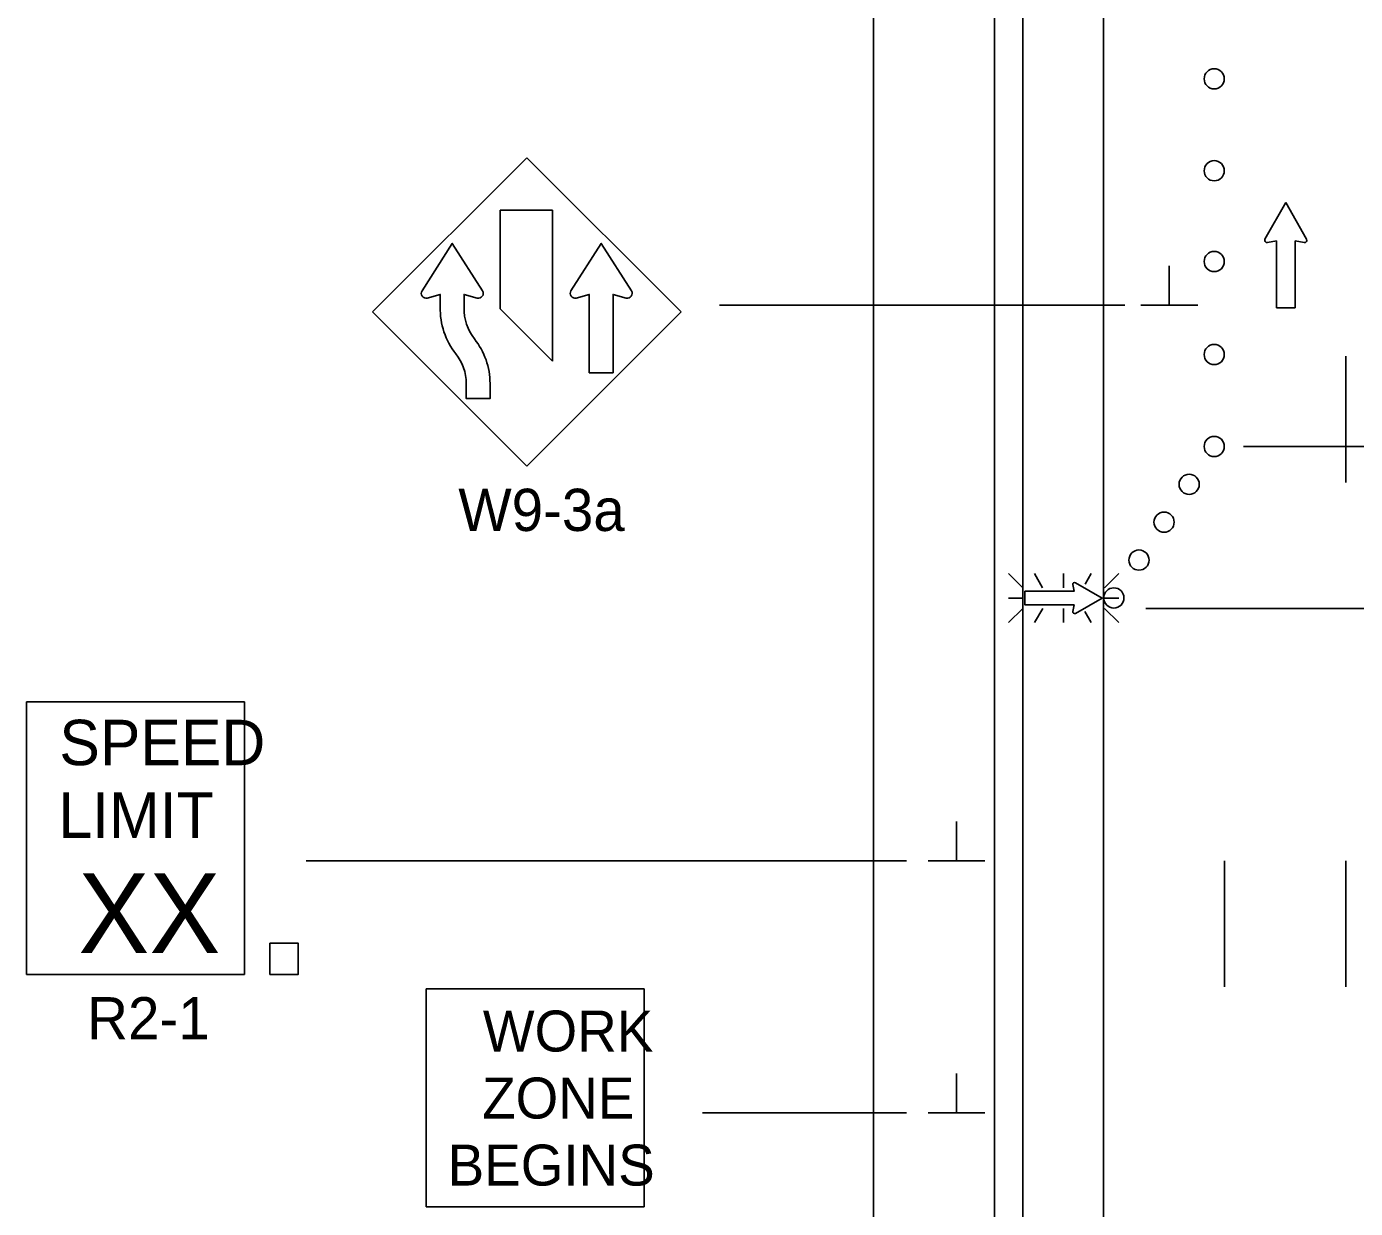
# Model space of a CAD drawing. Extents: x 16737 to 18482, y 6986 to 8195.
# Drawn here: x 16812.9 to 17076.2, y 7597.3 to 7831.6 of the extents above; entities that cross this region are included whole.
import ezdxf

# ---------------------------------------------------------------- set-up
doc = ezdxf.new("R2010")
doc.units = 0
for name, color, linetype in [('ALI_LEGAL_EX', 7, 'Continuous'), ('MT_SCRATCH_LEVEL_E', 7, 'Continuous'), ('PAVT_EDGE_EX', 7, 'Continuous'), ('TRAFFIC_SIGNS_PR', 7, 'Continuous'), ('TYPICAL_TEXT_DIMEN_PR', 7, 'Continuous')]:
    doc.layers.add(name, color=color, linetype=linetype)

msp = doc.modelspace()

# ---------------------------------------------------------------- linework, layer by layer
at = {"layer": 'ALI_LEGAL_EX'}
for p, q in [((16980.68, 8182.43), (16980.68, 7364.3)), ((17004.68, 8182.43), (17004.68, 7364.3))]:
    msp.add_line(p, q, dxfattribs=at)
for points in [[(17074.25, 7766.21), (17074.25, 7741.21)], [(17050.25, 7666.21), (17050.25, 7641.21)], [(17074.25, 7666.21), (17074.25, 7641.21)]]:
    msp.add_lwpolyline(points, dxfattribs=at)
at = {"layer": 'MT_SCRATCH_LEVEL_E'}
for p, q in [((17062.35, 7796.66), (17058.24, 7789.42)), ((17066.5, 7789.42), (17062.35, 7796.66)), ((17058.73, 7788.74), (17060.5, 7789.06)), ((17060.5, 7789.06), (17060.5, 7775.8)), ((17064.24, 7775.8), (17064.24, 7789.06)), ((17064.24, 7789.06), (17066.02, 7788.74)), ((17060.5, 7775.8), (17064.24, 7775.8))]:
    msp.add_line(p, q, dxfattribs=at)
for centre, start, end in [((17058.65, 7789.2), 150.4248, 279.9638), ((17066.09, 7789.2), 260.0362, 29.7731)]:
    msp.add_arc(centre, 0.463, start, end, dxfattribs=at)
at = {"layer": 'PAVT_EDGE_EX'}
for p, q in [((17010.25, 8166.21), (17010.25, 7372.95)), ((17026.25, 8166.21), (17026.25, 7372.95))]:
    msp.add_line(p, q, dxfattribs=at)
at = {"layer": 'TRAFFIC_SIGNS_PR'}
for p, q in [((16912.01, 7805.55), (16881.46, 7775)), ((16942.56, 7775), (16912.01, 7805.55)), ((16906.71, 7795.17), (16906.71, 7775.6)), ((16917.07, 7795.17), (16906.71, 7795.17)), ((16917.07, 7765.24), (16917.07, 7795.17)), ((16881.46, 7775), (16912.01, 7744.45)), ((16906.71, 7775.6), (16917.07, 7765.24)), ((16912.01, 7744.45), (16942.56, 7775)), ((17010.27, 7720.3), (17007.45, 7723.12)), ((17012.56, 7723.12), (17014.19, 7720.3)), ((17018.35, 7720.3), (17018.35, 7723.12)), ((17023.82, 7723.12), (17022.62, 7721.03)), ((17029.26, 7723.12), (17026.44, 7720.3)), ((17010.27, 7718.27), (17007.45, 7718.27)), ((17010.27, 7716.24), (17007.45, 7713.41)), ((17014.22, 7716.24), (17012.59, 7713.42)), ((17018.35, 7716.24), (17018.35, 7713.42)), ((17026.44, 7718.27), (17029.26, 7718.27)), ((17029.26, 7713.42), (17026.44, 7716.24)), ((17022.54, 7715.6), (17023.8, 7713.42)), ((16812.9, 7697.69), (16856.1, 7697.69)), ((16812.9, 7643.69), (16812.9, 7697.69)), ((16856.1, 7643.69), (16856.1, 7697.69)), ((16812.9, 7643.69), (16856.1, 7643.69)), ((16892.04, 7597.63), (16892.04, 7640.83)), ((16892.04, 7640.83), (16935.24, 7640.83)), ((16935.24, 7597.63), (16935.24, 7640.83)), ((16892.04, 7597.63), (16935.24, 7597.63))]:
    msp.add_line(p, q, dxfattribs=at)
for points in [[(16903.23, 7779.17), (16897.23, 7788.58), (16891.24, 7779.17)], [(16932.73, 7779.17), (16926.74, 7788.58), (16920.75, 7779.17)], [(16892.29, 7777.75), (16894.87, 7778.46), (16894.87, 7775.95)], [(16899.59, 7775.83), (16899.59, 7778.46), (16902.18, 7777.75)], [(16921.8, 7777.75), (16924.38, 7778.46), (16924.38, 7762.93), (16929.1, 7762.93), (16929.1, 7778.46), (16931.69, 7777.75)], [(16900.01, 7760.81), (16900, 7757.83), (16904.73, 7757.83), (16904.73, 7760.81)], [(17020.18, 7720.95), (17020.41, 7719.65), (17010.69, 7719.65), (17010.69, 7716.91), (17020.41, 7716.91), (17020.18, 7715.61)], [(17020.68, 7715.25), (17025.99, 7718.27), (17020.68, 7721.31)]]:
    msp.add_lwpolyline(points, dxfattribs=at)
msp.add_lwpolyline([(16861.12, 7643.69), (16866.71, 7643.69), (16866.71, 7649.86), (16861.12, 7649.86)], close=True, dxfattribs=at)
for centre in [(17048.19, 7821.19), (17048.19, 7802.98), (17048.19, 7784.98), (17048.19, 7766.55), (17048.19, 7748.33), (17043.22, 7740.82), (17038.25, 7733.32), (17033.28, 7725.81), (17028.31, 7718.31)]:
    msp.add_circle(centre, 2, dxfattribs=at)
for centre, radius, start, end in [((16892.04, 7778.66), 0.945, 147.5204, 285.3986), ((16902.43, 7778.66), 0.947, 254.6828, 32.2708), ((16899.06, 7766.36), 11.81, 74.68, 74.6808), ((16913.19, 7785.51), 11.81, 212.4569, 212.4665), ((16921.55, 7778.66), 0.946, 147.5497, 285.3316), ((16931.94, 7778.66), 0.943, 254.6778, 32.4665), ((16942.7, 7785.51), 11.81, 212.4569, 212.4665), ((16909.03, 7775.53), 14.17, 178.3293, 218.5427), ((16909.03, 7775.53), 9.45, 178.1936, 218.5465), ((16887.78, 7776.21), 11.81, 358.1894, 0.0048), ((16890.55, 7760.81), 14.17, 0, 38.5422), ((16890.55, 7760.81), 9.45, 0, 38.5457), ((17020.52, 7721.01), 0.341, 61.4833, 189.9593), ((17020.51, 7715.55), 0.341, 170.7308, 298.8916)]:
    msp.add_arc(centre, radius, start, end, dxfattribs=at)
at = {"layer": 'TYPICAL_TEXT_DIMEN_PR'}
for p, q in [((17039.29, 7776.36), (17039.29, 7784.15)), ((17030.46, 7776.36), (16950.18, 7776.36)), ((17044.92, 7776.36), (17033.67, 7776.36)), ((17054, 7748.33), (17198.06, 7748.33)), ((17034.65, 7716.23), (17163.25, 7716.23)), ((16997.12, 7666.23), (16997.12, 7674.02)), ((16868.3, 7666.23), (16987.25, 7666.23)), ((16991.5, 7666.23), (17002.75, 7666.23)), ((16997.12, 7616.23), (16997.12, 7624.02)), ((16987.25, 7616.23), (16946.83, 7616.23)), ((16991.5, 7616.23), (17002.75, 7616.23))]:
    msp.add_line(p, q, dxfattribs=at)

# ---------------------------------------------------------------- texts
at = {"layer": 'TRAFFIC_SIGNS_PR'}
for s, height, p in [('W9-3a', 8.37, (16898.44, 7731.58)), ('SPEED', 9, (16819.39, 7685.16)), ('LIMIT', 9, (16819.21, 7670.76)), ('XX', 15.785, (16823.15, 7647.92)), ('R2-1', 8.37, (16824.91, 7630.82)), ('WORK', 8.119, (16903.29, 7628.41)), ('ZONE', 8.119, (16903.15, 7615.13)), ('BEGINS', 8.119, (16896.32, 7601.84))]:
    msp.add_text(s, height=height, dxfattribs=at).set_placement(p)

doc.saveas('drawing.dxf')
